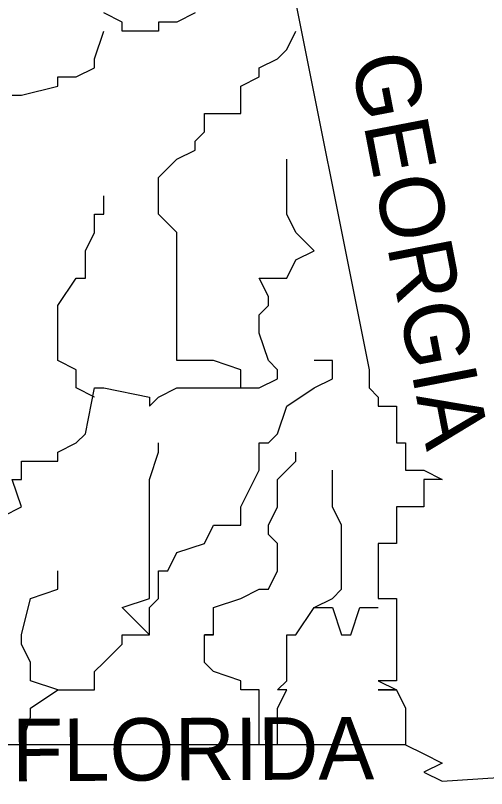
# Model space of a CAD drawing. Extents: x -12822 to 16384, y -6351 to 1913.
# Drawn here: x 75.36 to 88.88, y -1810.47 to -1788.26 of the extents above; entities that cross this region are included whole.
import ezdxf

# ---------------------------------------------------------------- set-up
doc = ezdxf.new("R2010")
doc.units = 0
doc.layers.add('great seal', color=7, linetype='Continuous')

msp = doc.modelspace()

# ---------------------------------------------------------------- linework, layer by layer
at = {"layer": 'great seal'}
msp.add_line((77.627, -1799.225), (77.627, -1799.225), dxfattribs=at)
msp.add_line((77.627, -1799.225), (77.627, -1799.225), dxfattribs=at)
msp.add_line((77.627, -1799.225), (77.627, -1799.225), dxfattribs=at)
msp.add_line((77.627, -1799.225), (77.627, -1799.225), dxfattribs=at)
msp.add_line((77.627, -1799.225), (77.627, -1799.225), dxfattribs=at)
msp.add_line((77.627, -1799.225), (77.627, -1799.225), dxfattribs=at)
for points in [[(83.145, -1786.612), (85.51, -1798.437), (85.51, -1798.962), (85.773, -1799.225), (85.773, -1799.488), (85.773, -1799.488), (86.299, -1799.488), (86.299, -1800.276), (86.299, -1800.539), (86.561, -1800.539), (86.561, -1800.802), (86.561, -1800.802), (86.561, -1801.064), (86.561, -1801.327), (87.087, -1801.327), (87.612, -1801.59), (87.087, -1801.59), (87.087, -1802.378), (87.087, -1802.378), (86.561, -1802.378), (86.561, -1802.378), (86.561, -1802.378), (86.561, -1802.378), (86.299, -1802.378), (86.299, -1802.378), (86.299, -1802.378), (86.299, -1802.641), (86.299, -1802.904), (86.299, -1802.904), (86.299, -1802.904), (86.299, -1802.904), (86.299, -1802.904), (86.299, -1803.167), (86.299, -1803.167), (86.299, -1803.167), (86.299, -1803.429), (86.299, -1803.429), (85.773, -1803.429), (85.773, -1803.429), (85.773, -1803.429), (85.773, -1803.692), (85.773, -1803.692), (85.773, -1804.218), (85.773, -1804.218), (85.773, -1804.218), (85.773, -1804.218), (85.773, -1804.218), (85.773, -1804.218), (85.773, -1804.218), (85.773, -1804.743), (85.773, -1804.743), (85.773, -1804.743), (85.773, -1804.743), (85.773, -1804.743), (85.773, -1804.743), (85.773, -1805.006), (86.299, -1805.006), (86.299, -1805.269), (86.299, -1805.269), (86.299, -1805.269), (86.299, -1806.057), (86.299, -1806.057), (86.299, -1806.057), (86.299, -1806.057), (86.299, -1806.057), (86.299, -1806.057), (86.299, -1806.32), (86.299, -1806.845), (86.299, -1806.845), (86.299, -1806.845), (86.299, -1807.108), (86.299, -1807.108), (86.299, -1807.371), (86.299, -1807.371), (85.773, -1807.371), (85.773, -1807.371), (85.773, -1807.371), (85.773, -1807.371), (86.299, -1807.634), (86.299, -1807.634), (85.773, -1807.634), (86.299, -1807.634), (86.299, -1807.634), (86.299, -1807.634), (86.561, -1808.159), (86.561, -1808.159), (86.561, -1808.422), (86.561, -1808.422), (86.561, -1809.21), (73.16, -1809.21)], [(83.145, -1786.612), (85.51, -1798.437), (85.51, -1798.962), (85.773, -1799.225), (85.773, -1799.488), (85.773, -1799.488), (86.299, -1799.488), (86.299, -1800.276), (86.299, -1800.539), (86.561, -1800.539), (86.561, -1800.802), (86.561, -1800.802), (86.561, -1801.064), (86.561, -1801.327), (87.087, -1801.327), (87.612, -1801.59), (87.087, -1801.59), (87.087, -1802.378), (87.087, -1802.378), (86.561, -1802.378), (86.561, -1802.378), (86.561, -1802.378), (86.561, -1802.378), (86.299, -1802.378), (86.299, -1802.378), (86.299, -1802.378), (86.299, -1802.641), (86.299, -1802.904), (86.299, -1802.904), (86.299, -1802.904), (86.299, -1802.904), (86.299, -1802.904), (86.299, -1803.167), (86.299, -1803.167), (86.299, -1803.167), (86.299, -1803.429), (86.299, -1803.429), (85.773, -1803.429), (85.773, -1803.429), (85.773, -1803.429), (85.773, -1803.692), (85.773, -1803.692), (85.773, -1804.218), (85.773, -1804.218), (85.773, -1804.218), (85.773, -1804.218), (85.773, -1804.218), (85.773, -1804.218), (85.773, -1804.218), (85.773, -1804.743), (85.773, -1804.743), (85.773, -1804.743), (85.773, -1804.743), (85.773, -1804.743), (85.773, -1804.743), (85.773, -1805.006), (86.299, -1805.006), (86.299, -1805.269), (86.299, -1805.269), (86.299, -1805.269), (86.299, -1806.057), (86.299, -1806.057), (86.299, -1806.057), (86.299, -1806.057), (86.299, -1806.057), (86.299, -1806.057), (86.299, -1806.32), (86.299, -1806.845), (86.299, -1806.845), (86.299, -1806.845), (86.299, -1807.108), (86.299, -1807.108), (86.299, -1807.371), (86.299, -1807.371), (85.773, -1807.371), (85.773, -1807.371), (85.773, -1807.371), (85.773, -1807.371), (86.299, -1807.634), (86.299, -1807.634), (85.773, -1807.634), (86.299, -1807.634), (86.299, -1807.634), (86.299, -1807.634), (86.561, -1808.159), (86.561, -1808.159), (86.561, -1808.422), (86.561, -1808.422), (86.561, -1809.21), (73.16, -1809.21)], [(83.145, -1786.612), (85.51, -1798.437), (85.51, -1798.962), (85.773, -1799.225), (85.773, -1799.488), (85.773, -1799.488), (86.299, -1799.488), (86.299, -1800.276), (86.299, -1800.539), (86.561, -1800.539), (86.561, -1800.802), (86.561, -1800.802), (86.561, -1801.064), (86.561, -1801.327), (87.087, -1801.327), (87.612, -1801.59), (87.087, -1801.59), (87.087, -1802.378), (87.087, -1802.378), (86.561, -1802.378), (86.561, -1802.378), (86.561, -1802.378), (86.561, -1802.378), (86.299, -1802.378), (86.299, -1802.378), (86.299, -1802.378), (86.299, -1802.641), (86.299, -1802.904), (86.299, -1802.904), (86.299, -1802.904), (86.299, -1802.904), (86.299, -1802.904), (86.299, -1803.167), (86.299, -1803.167), (86.299, -1803.167), (86.299, -1803.429), (86.299, -1803.429), (85.773, -1803.429), (85.773, -1803.429), (85.773, -1803.429), (85.773, -1803.692), (85.773, -1803.692), (85.773, -1804.218), (85.773, -1804.218), (85.773, -1804.218), (85.773, -1804.218), (85.773, -1804.218), (85.773, -1804.218), (85.773, -1804.218), (85.773, -1804.743), (85.773, -1804.743), (85.773, -1804.743), (85.773, -1804.743), (85.773, -1804.743), (85.773, -1804.743), (85.773, -1805.006), (86.299, -1805.006), (86.299, -1805.269), (86.299, -1805.269), (86.299, -1805.269), (86.299, -1806.057), (86.299, -1806.057), (86.299, -1806.057), (86.299, -1806.057), (86.299, -1806.057), (86.299, -1806.057), (86.299, -1806.32), (86.299, -1806.845), (86.299, -1806.845), (86.299, -1806.845), (86.299, -1807.108), (86.299, -1807.108), (86.299, -1807.371), (86.299, -1807.371), (85.773, -1807.371), (85.773, -1807.371), (85.773, -1807.371), (85.773, -1807.371), (86.299, -1807.634), (86.299, -1807.634), (85.773, -1807.634), (86.299, -1807.634), (86.299, -1807.634), (86.299, -1807.634), (86.561, -1808.159), (86.561, -1808.159), (86.561, -1808.422), (86.561, -1808.422), (86.561, -1809.21), (73.16, -1809.21)], [(80.518, -1788.189), (79.992, -1788.452), (79.729, -1788.452), (79.467, -1788.452), (79.467, -1788.715), (79.204, -1788.715), (79.204, -1788.715), (78.416, -1788.715), (78.416, -1788.715), (78.416, -1788.452), (77.89, -1788.189)], [(80.518, -1788.189), (79.992, -1788.452), (79.729, -1788.452), (79.467, -1788.452), (79.467, -1788.715), (79.204, -1788.715), (79.204, -1788.715), (78.416, -1788.715), (78.416, -1788.715), (78.416, -1788.452), (77.89, -1788.189)], [(80.518, -1788.189), (79.992, -1788.452), (79.729, -1788.452), (79.467, -1788.452), (79.467, -1788.715), (79.204, -1788.715), (79.204, -1788.715), (78.416, -1788.715), (78.416, -1788.715), (78.416, -1788.452), (77.89, -1788.189)], [(75.262, -1790.554), (75.525, -1790.554), (75.525, -1790.554), (76.576, -1790.291), (76.576, -1790.028), (77.102, -1790.028), (77.627, -1789.766), (77.627, -1789.503), (77.89, -1788.715)], [(75.262, -1790.554), (75.525, -1790.554), (75.525, -1790.554), (76.576, -1790.291), (76.576, -1790.028), (77.102, -1790.028), (77.627, -1789.766), (77.627, -1789.503), (77.89, -1788.715)], [(75.262, -1790.554), (75.525, -1790.554), (75.525, -1790.554), (76.576, -1790.291), (76.576, -1790.028), (77.102, -1790.028), (77.627, -1789.766), (77.627, -1789.503), (77.89, -1788.715)], [(81.832, -1798.962), (81.832, -1798.437), (81.043, -1798.174), (80.78, -1798.174), (79.992, -1798.174), (79.992, -1796.86), (79.992, -1796.86), (79.992, -1796.597), (79.992, -1795.809), (79.992, -1795.284), (79.992, -1794.495), (79.467, -1793.97), (79.467, -1792.919), (79.992, -1792.393), (80.518, -1792.13), (80.518, -1791.868), (80.78, -1791.605), (80.78, -1791.079), (81.832, -1791.079), (81.832, -1790.554), (81.832, -1790.291), (82.357, -1790.028), (82.357, -1789.766), (82.883, -1789.503), (83.145, -1789.24), (83.408, -1788.715)], [(81.832, -1798.962), (81.832, -1798.437), (81.043, -1798.174), (80.78, -1798.174), (79.992, -1798.174), (79.992, -1796.86), (79.992, -1796.86), (79.992, -1796.597), (79.992, -1795.809), (79.992, -1795.284), (79.992, -1794.495), (79.467, -1793.97), (79.467, -1792.919), (79.992, -1792.393), (80.518, -1792.13), (80.518, -1791.868), (80.78, -1791.605), (80.78, -1791.079), (81.832, -1791.079), (81.832, -1790.554), (81.832, -1790.291), (82.357, -1790.028), (82.357, -1789.766), (82.883, -1789.503), (83.145, -1789.24), (83.408, -1788.715)], [(81.832, -1798.962), (81.832, -1798.437), (81.043, -1798.174), (80.78, -1798.174), (79.992, -1798.174), (79.992, -1796.86), (79.992, -1796.86), (79.992, -1796.597), (79.992, -1795.809), (79.992, -1795.284), (79.992, -1794.495), (79.467, -1793.97), (79.467, -1792.919), (79.992, -1792.393), (80.518, -1792.13), (80.518, -1791.868), (80.78, -1791.605), (80.78, -1791.079), (81.832, -1791.079), (81.832, -1790.554), (81.832, -1790.291), (82.357, -1790.028), (82.357, -1789.766), (82.883, -1789.503), (83.145, -1789.24), (83.408, -1788.715)], [(75, -1802.641), (75.525, -1802.378), (75.262, -1801.59), (75.525, -1801.59), (75.525, -1801.064), (76.576, -1801.064), (76.576, -1800.802), (76.576, -1800.802), (77.102, -1800.539), (77.365, -1800.276), (77.627, -1798.962), (77.89, -1798.962), (79.204, -1799.225), (79.204, -1799.488), (79.467, -1799.225), (79.992, -1798.962), (80.78, -1798.962), (81.832, -1798.962), (82.357, -1798.962), (82.883, -1798.7), (82.883, -1798.437), (82.62, -1798.174), (82.62, -1798.174), (82.357, -1797.386), (82.357, -1796.86), (82.62, -1796.597), (82.62, -1796.335), (82.357, -1795.809), (83.145, -1795.809), (83.408, -1795.284), (83.934, -1795.021), (83.408, -1794.495), (83.408, -1794.495), (83.145, -1793.97), (83.145, -1793.444), (83.145, -1792.393)], [(75, -1802.641), (75.525, -1802.378), (75.262, -1801.59), (75.525, -1801.59), (75.525, -1801.064), (76.576, -1801.064), (76.576, -1800.802), (76.576, -1800.802), (77.102, -1800.539), (77.365, -1800.276), (77.627, -1798.962), (77.89, -1798.962), (79.204, -1799.225), (79.204, -1799.488), (79.467, -1799.225), (79.992, -1798.962), (80.78, -1798.962), (81.832, -1798.962), (82.357, -1798.962), (82.883, -1798.7), (82.883, -1798.437), (82.62, -1798.174), (82.62, -1798.174), (82.357, -1797.386), (82.357, -1796.86), (82.62, -1796.597), (82.62, -1796.335), (82.357, -1795.809), (83.145, -1795.809), (83.408, -1795.284), (83.934, -1795.021), (83.408, -1794.495), (83.408, -1794.495), (83.145, -1793.97), (83.145, -1793.444), (83.145, -1792.393)], [(75, -1802.641), (75.525, -1802.378), (75.262, -1801.59), (75.525, -1801.59), (75.525, -1801.064), (76.576, -1801.064), (76.576, -1800.802), (76.576, -1800.802), (77.102, -1800.539), (77.365, -1800.276), (77.627, -1798.962), (77.89, -1798.962), (79.204, -1799.225), (79.204, -1799.488), (79.467, -1799.225), (79.992, -1798.962), (80.78, -1798.962), (81.832, -1798.962), (82.357, -1798.962), (82.883, -1798.7), (82.883, -1798.437), (82.62, -1798.174), (82.62, -1798.174), (82.357, -1797.386), (82.357, -1796.86), (82.62, -1796.597), (82.62, -1796.335), (82.357, -1795.809), (83.145, -1795.809), (83.408, -1795.284), (83.934, -1795.021), (83.408, -1794.495), (83.408, -1794.495), (83.145, -1793.97), (83.145, -1793.444), (83.145, -1792.393)], [(77.627, -1799.225), (77.102, -1798.962), (77.102, -1798.7), (77.102, -1798.437), (76.576, -1798.174), (76.576, -1797.386), (76.576, -1796.86), (76.576, -1796.597), (76.576, -1796.597), (77.102, -1795.809), (77.365, -1795.809), (77.365, -1795.021), (77.627, -1794.495), (77.627, -1794.495), (77.627, -1793.97), (77.89, -1793.97), (77.89, -1793.444)], [(77.627, -1799.225), (77.102, -1798.962), (77.102, -1798.7), (77.102, -1798.437), (76.576, -1798.174), (76.576, -1797.386), (76.576, -1796.86), (76.576, -1796.597), (76.576, -1796.597), (77.102, -1795.809), (77.365, -1795.809), (77.365, -1795.021), (77.627, -1794.495), (77.627, -1794.495), (77.627, -1793.97), (77.89, -1793.97), (77.89, -1793.444)], [(77.627, -1799.225), (77.102, -1798.962), (77.102, -1798.7), (77.102, -1798.437), (76.576, -1798.174), (76.576, -1797.386), (76.576, -1796.86), (76.576, -1796.597), (76.576, -1796.597), (77.102, -1795.809), (77.365, -1795.809), (77.365, -1795.021), (77.627, -1794.495), (77.627, -1794.495), (77.627, -1793.97), (77.89, -1793.97), (77.89, -1793.444)], [(79.204, -1806.057), (79.204, -1806.057), (79.204, -1805.269), (79.467, -1805.006), (79.467, -1804.743), (79.467, -1804.218), (79.729, -1804.218), (79.992, -1803.692), (80.78, -1803.429), (81.043, -1802.904), (81.832, -1802.904), (81.832, -1802.378), (82.357, -1801.327), (82.357, -1800.802), (82.357, -1800.802), (82.357, -1800.539), (82.62, -1800.539), (82.883, -1800.276), (83.145, -1799.488), (83.934, -1798.962), (84.459, -1798.7), (84.459, -1798.437), (84.459, -1798.174), (83.934, -1798.174)], [(79.204, -1806.057), (79.204, -1806.057), (79.204, -1805.269), (79.467, -1805.006), (79.467, -1804.743), (79.467, -1804.218), (79.729, -1804.218), (79.992, -1803.692), (80.78, -1803.429), (81.043, -1802.904), (81.832, -1802.904), (81.832, -1802.378), (82.357, -1801.327), (82.357, -1800.802), (82.357, -1800.802), (82.357, -1800.539), (82.62, -1800.539), (82.883, -1800.276), (83.145, -1799.488), (83.934, -1798.962), (84.459, -1798.7), (84.459, -1798.437), (84.459, -1798.174), (83.934, -1798.174)], [(79.204, -1806.057), (79.204, -1806.057), (79.204, -1805.269), (79.467, -1805.006), (79.467, -1804.743), (79.467, -1804.218), (79.729, -1804.218), (79.992, -1803.692), (80.78, -1803.429), (81.043, -1802.904), (81.832, -1802.904), (81.832, -1802.378), (82.357, -1801.327), (82.357, -1800.802), (82.357, -1800.802), (82.357, -1800.539), (82.62, -1800.539), (82.883, -1800.276), (83.145, -1799.488), (83.934, -1798.962), (84.459, -1798.7), (84.459, -1798.437), (84.459, -1798.174), (83.934, -1798.174)], [(76.576, -1807.634), (76.576, -1807.634), (77.102, -1807.634), (77.365, -1807.634), (77.627, -1807.634), (77.627, -1807.371), (77.627, -1807.108), (77.89, -1806.845), (78.416, -1806.32), (78.416, -1806.057), (79.204, -1806.057), (79.204, -1806.057), (78.416, -1805.269), (79.204, -1805.006), (79.204, -1804.743), (79.204, -1804.218), (79.204, -1803.692), (79.204, -1803.429), (79.204, -1802.904), (79.204, -1802.904), (79.204, -1802.378), (79.204, -1801.59), (79.467, -1800.802), (79.467, -1800.802), (79.467, -1800.539)], [(76.576, -1807.634), (76.576, -1807.634), (77.102, -1807.634), (77.365, -1807.634), (77.627, -1807.634), (77.627, -1807.371), (77.627, -1807.108), (77.89, -1806.845), (78.416, -1806.32), (78.416, -1806.057), (79.204, -1806.057), (79.204, -1806.057), (78.416, -1805.269), (79.204, -1805.006), (79.204, -1804.743), (79.204, -1804.218), (79.204, -1803.692), (79.204, -1803.429), (79.204, -1802.904), (79.204, -1802.904), (79.204, -1802.378), (79.204, -1801.59), (79.467, -1800.802), (79.467, -1800.802), (79.467, -1800.539)], [(76.576, -1807.634), (76.576, -1807.634), (77.102, -1807.634), (77.365, -1807.634), (77.627, -1807.634), (77.627, -1807.371), (77.627, -1807.108), (77.89, -1806.845), (78.416, -1806.32), (78.416, -1806.057), (79.204, -1806.057), (79.204, -1806.057), (78.416, -1805.269), (79.204, -1805.006), (79.204, -1804.743), (79.204, -1804.218), (79.204, -1803.692), (79.204, -1803.429), (79.204, -1802.904), (79.204, -1802.904), (79.204, -1802.378), (79.204, -1801.59), (79.467, -1800.802), (79.467, -1800.802), (79.467, -1800.539)], [(82.357, -1809.21), (82.357, -1808.422), (82.357, -1808.159), (82.357, -1807.634), (82.357, -1807.634), (81.832, -1807.634), (81.832, -1807.371), (81.043, -1807.108), (80.78, -1806.845), (80.78, -1806.32), (80.78, -1806.057), (81.043, -1806.057), (80.78, -1806.057), (81.043, -1806.057), (81.043, -1805.269), (81.832, -1805.006), (82.357, -1804.743), (82.357, -1804.743), (82.62, -1804.743), (82.883, -1804.218), (82.883, -1804.218), (82.883, -1803.692), (82.883, -1803.429), (82.883, -1803.429), (82.62, -1803.167), (82.62, -1802.904), (82.883, -1802.378), (82.883, -1801.59), (83.145, -1801.327), (83.408, -1801.064), (83.408, -1800.802)], [(82.357, -1809.21), (82.357, -1808.422), (82.357, -1808.159), (82.357, -1807.634), (82.357, -1807.634), (81.832, -1807.634), (81.832, -1807.371), (81.043, -1807.108), (80.78, -1806.845), (80.78, -1806.32), (80.78, -1806.057), (81.043, -1806.057), (80.78, -1806.057), (81.043, -1806.057), (81.043, -1805.269), (81.832, -1805.006), (82.357, -1804.743), (82.357, -1804.743), (82.62, -1804.743), (82.883, -1804.218), (82.883, -1804.218), (82.883, -1803.692), (82.883, -1803.429), (82.883, -1803.429), (82.62, -1803.167), (82.62, -1802.904), (82.883, -1802.378), (82.883, -1801.59), (83.145, -1801.327), (83.408, -1801.064), (83.408, -1800.802)], [(82.357, -1809.21), (82.357, -1808.422), (82.357, -1808.159), (82.357, -1807.634), (82.357, -1807.634), (81.832, -1807.634), (81.832, -1807.371), (81.043, -1807.108), (80.78, -1806.845), (80.78, -1806.32), (80.78, -1806.057), (81.043, -1806.057), (80.78, -1806.057), (81.043, -1806.057), (81.043, -1805.269), (81.832, -1805.006), (82.357, -1804.743), (82.357, -1804.743), (82.62, -1804.743), (82.883, -1804.218), (82.883, -1804.218), (82.883, -1803.692), (82.883, -1803.429), (82.883, -1803.429), (82.62, -1803.167), (82.62, -1802.904), (82.883, -1802.378), (82.883, -1801.59), (83.145, -1801.327), (83.408, -1801.064), (83.408, -1800.802)], [(83.934, -1805.269), (83.934, -1805.269), (84.459, -1805.006), (84.722, -1804.743), (84.722, -1804.743), (84.722, -1804.218), (84.722, -1803.692), (84.722, -1803.429), (84.722, -1803.167), (84.722, -1802.904), (84.459, -1802.378), (84.459, -1802.378), (84.459, -1801.327)], [(83.934, -1805.269), (83.934, -1805.269), (84.459, -1805.006), (84.722, -1804.743), (84.722, -1804.743), (84.722, -1804.218), (84.722, -1803.692), (84.722, -1803.429), (84.722, -1803.167), (84.722, -1802.904), (84.459, -1802.378), (84.459, -1802.378), (84.459, -1801.327)], [(83.934, -1805.269), (83.934, -1805.269), (84.459, -1805.006), (84.722, -1804.743), (84.722, -1804.743), (84.722, -1804.218), (84.722, -1803.692), (84.722, -1803.429), (84.722, -1803.167), (84.722, -1802.904), (84.459, -1802.378), (84.459, -1802.378), (84.459, -1801.327)], [(75.525, -1809.21), (75.788, -1808.422), (75.788, -1808.159), (76.576, -1807.634), (76.576, -1807.634), (76.576, -1807.634), (75.788, -1807.371), (75.788, -1807.108), (75.788, -1806.845), (75.525, -1806.32), (75.525, -1806.057), (75.525, -1806.057), (75.788, -1805.006), (76.576, -1804.743), (76.576, -1804.218)], [(75.525, -1809.21), (75.788, -1808.422), (75.788, -1808.159), (76.576, -1807.634), (76.576, -1807.634), (76.576, -1807.634), (75.788, -1807.371), (75.788, -1807.108), (75.788, -1806.845), (75.525, -1806.32), (75.525, -1806.057), (75.525, -1806.057), (75.788, -1805.006), (76.576, -1804.743), (76.576, -1804.218)], [(75.525, -1809.21), (75.788, -1808.422), (75.788, -1808.159), (76.576, -1807.634), (76.576, -1807.634), (76.576, -1807.634), (75.788, -1807.371), (75.788, -1807.108), (75.788, -1806.845), (75.525, -1806.32), (75.525, -1806.057), (75.525, -1806.057), (75.788, -1805.006), (76.576, -1804.743), (76.576, -1804.218)], [(82.883, -1809.21), (82.883, -1808.422), (82.883, -1808.422), (82.883, -1808.159), (83.145, -1807.634), (82.883, -1807.634), (83.145, -1807.371), (83.145, -1807.108), (83.145, -1806.845), (83.145, -1806.845), (83.145, -1806.32), (83.145, -1806.057), (83.408, -1806.057), (83.934, -1805.269), (84.459, -1805.269), (84.722, -1806.057), (84.985, -1806.057), (85.247, -1805.269), (85.51, -1805.269), (85.773, -1805.269)], [(82.883, -1809.21), (82.883, -1808.422), (82.883, -1808.422), (82.883, -1808.159), (83.145, -1807.634), (82.883, -1807.634), (83.145, -1807.371), (83.145, -1807.108), (83.145, -1806.845), (83.145, -1806.845), (83.145, -1806.32), (83.145, -1806.057), (83.408, -1806.057), (83.934, -1805.269), (84.459, -1805.269), (84.722, -1806.057), (84.985, -1806.057), (85.247, -1805.269), (85.51, -1805.269), (85.773, -1805.269)], [(82.883, -1809.21), (82.883, -1808.422), (82.883, -1808.422), (82.883, -1808.159), (83.145, -1807.634), (82.883, -1807.634), (83.145, -1807.371), (83.145, -1807.108), (83.145, -1806.845), (83.145, -1806.845), (83.145, -1806.32), (83.145, -1806.057), (83.408, -1806.057), (83.934, -1805.269), (84.459, -1805.269), (84.722, -1806.057), (84.985, -1806.057), (85.247, -1805.269), (85.51, -1805.269), (85.773, -1805.269)], [(86.561, -1809.21), (87.087, -1809.473), (87.087, -1809.473), (87.612, -1809.736), (87.087, -1809.998), (87.612, -1810.261), (91.554, -1809.998)], [(86.561, -1809.21), (87.087, -1809.473), (87.087, -1809.473), (87.612, -1809.736), (87.087, -1809.998), (87.612, -1810.261), (91.554, -1809.998)], [(86.561, -1809.21), (87.087, -1809.473), (87.087, -1809.473), (87.612, -1809.736), (87.087, -1809.998), (87.612, -1810.261), (91.554, -1809.998)]]:
    msp.add_lwpolyline(points, dxfattribs=at)
for radius in [22.994, 22.994, 22.994, 22.389, 22.389, 22.389, 17.779, 17.779, 17.779, 17.222, 17.222, 17.222]:
    msp.add_circle((77.645, -1799.409), radius, dxfattribs=at)

# ---------------------------------------------------------------- texts
for s, height, rotation, p in [('GEORGIA', 1.8446, 280.9296, (84.985, -1789.503)), ('GEORGIA', 1.8446, 280.9296, (84.985, -1789.503)), ('GEORGIA', 1.8446, 280.9296, (84.985, -1789.503)), ('FLORIDA', 1.7941, 0.3238, (75.262, -1810.261)), ('FLORIDA', 1.7941, 0.3238, (75.262, -1810.261)), ('FLORIDA', 1.7941, 0.3238, (75.262, -1810.261))]:
    msp.add_text(s, height=height, rotation=rotation, dxfattribs=at).set_placement(p)

doc.saveas('drawing.dxf')
